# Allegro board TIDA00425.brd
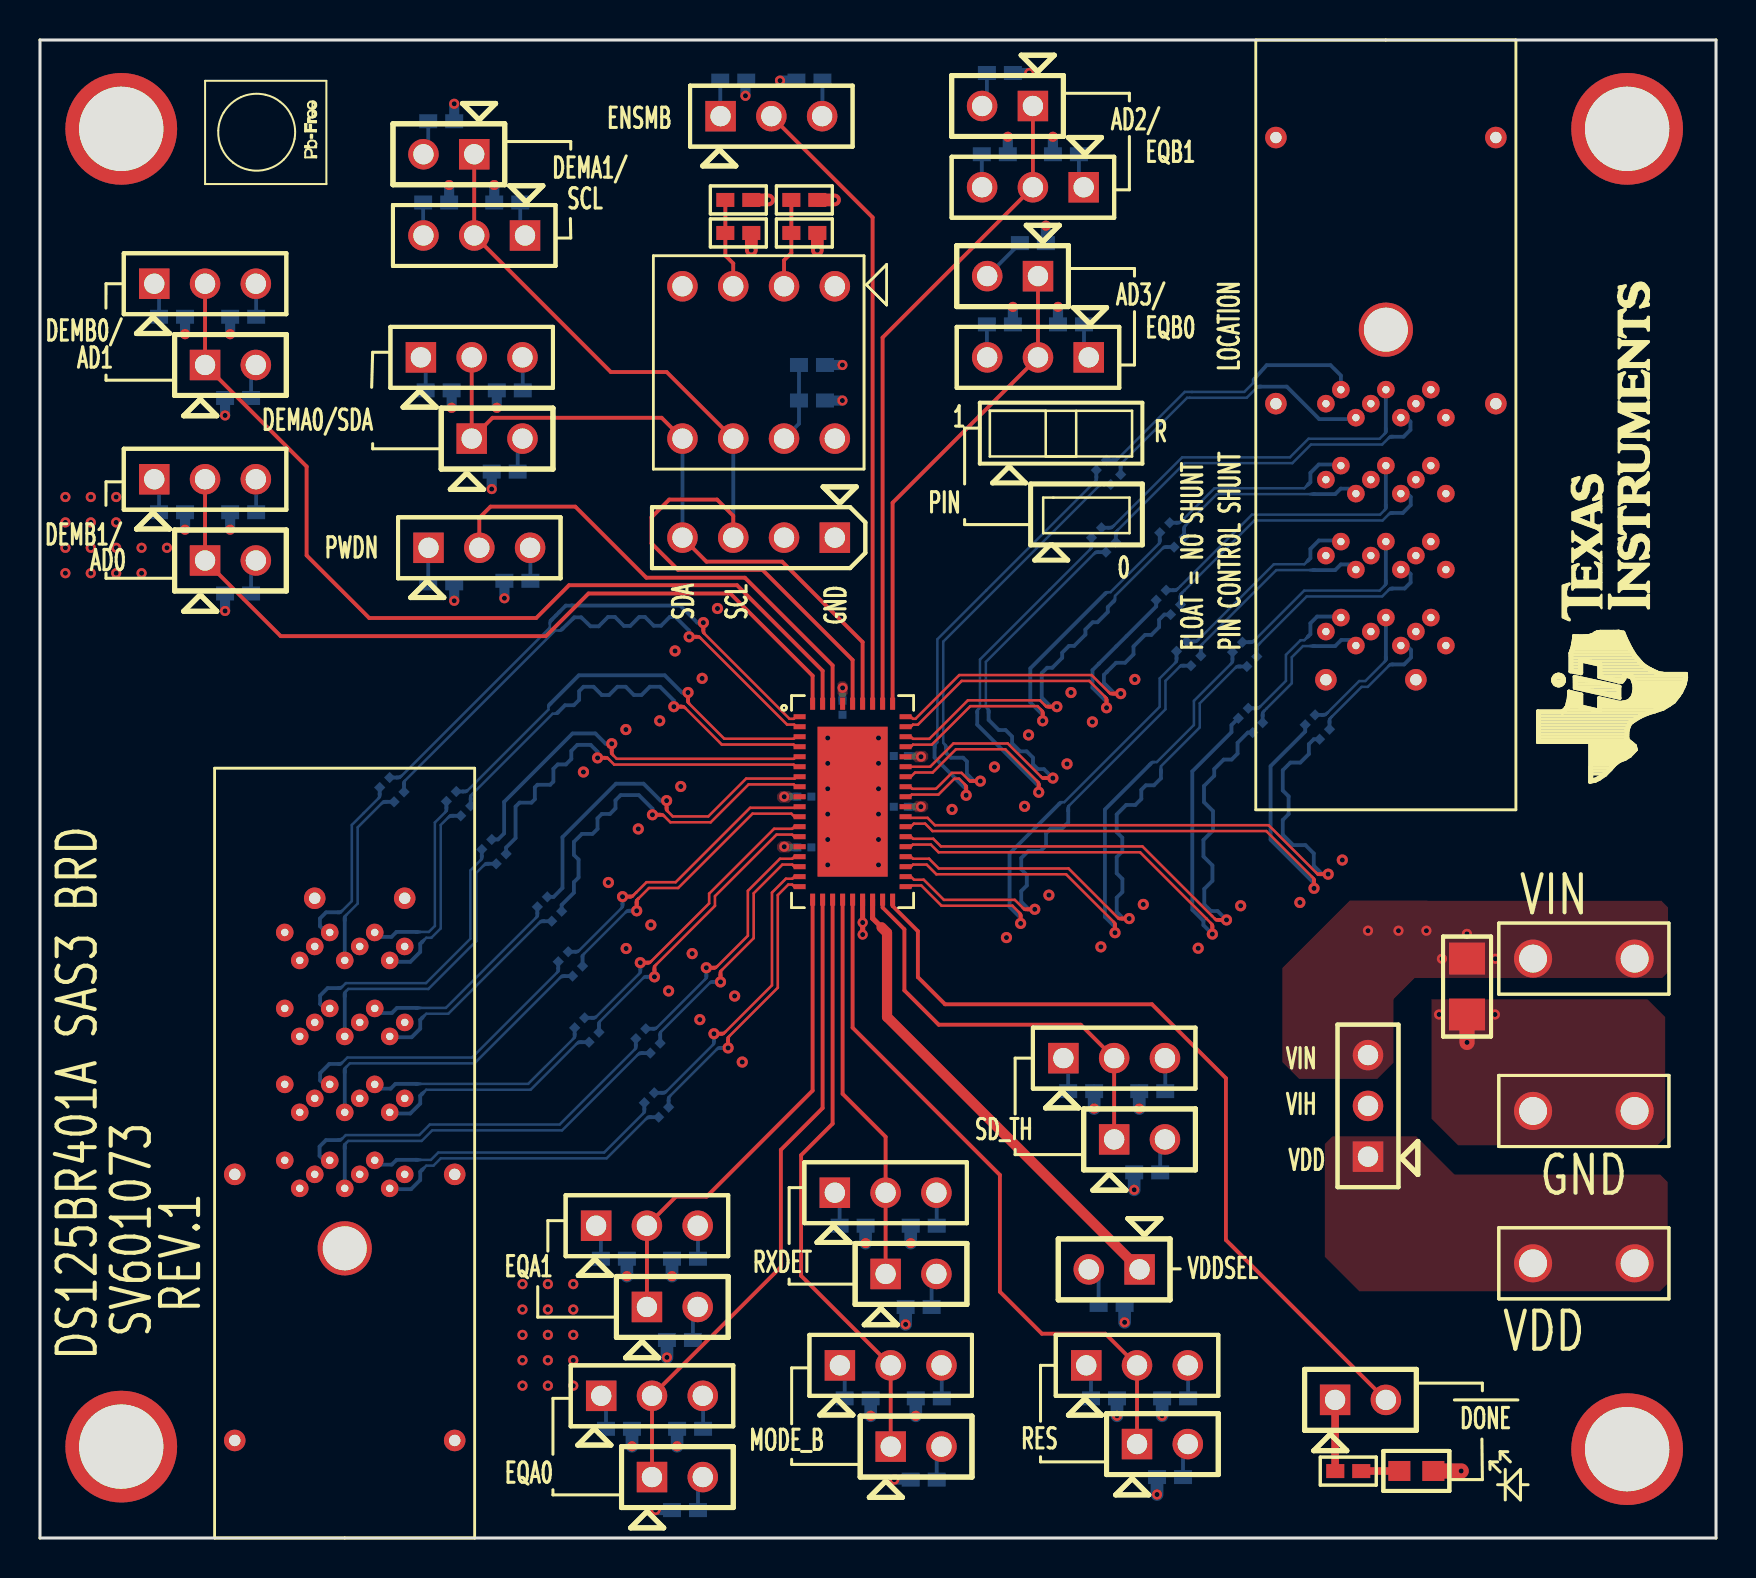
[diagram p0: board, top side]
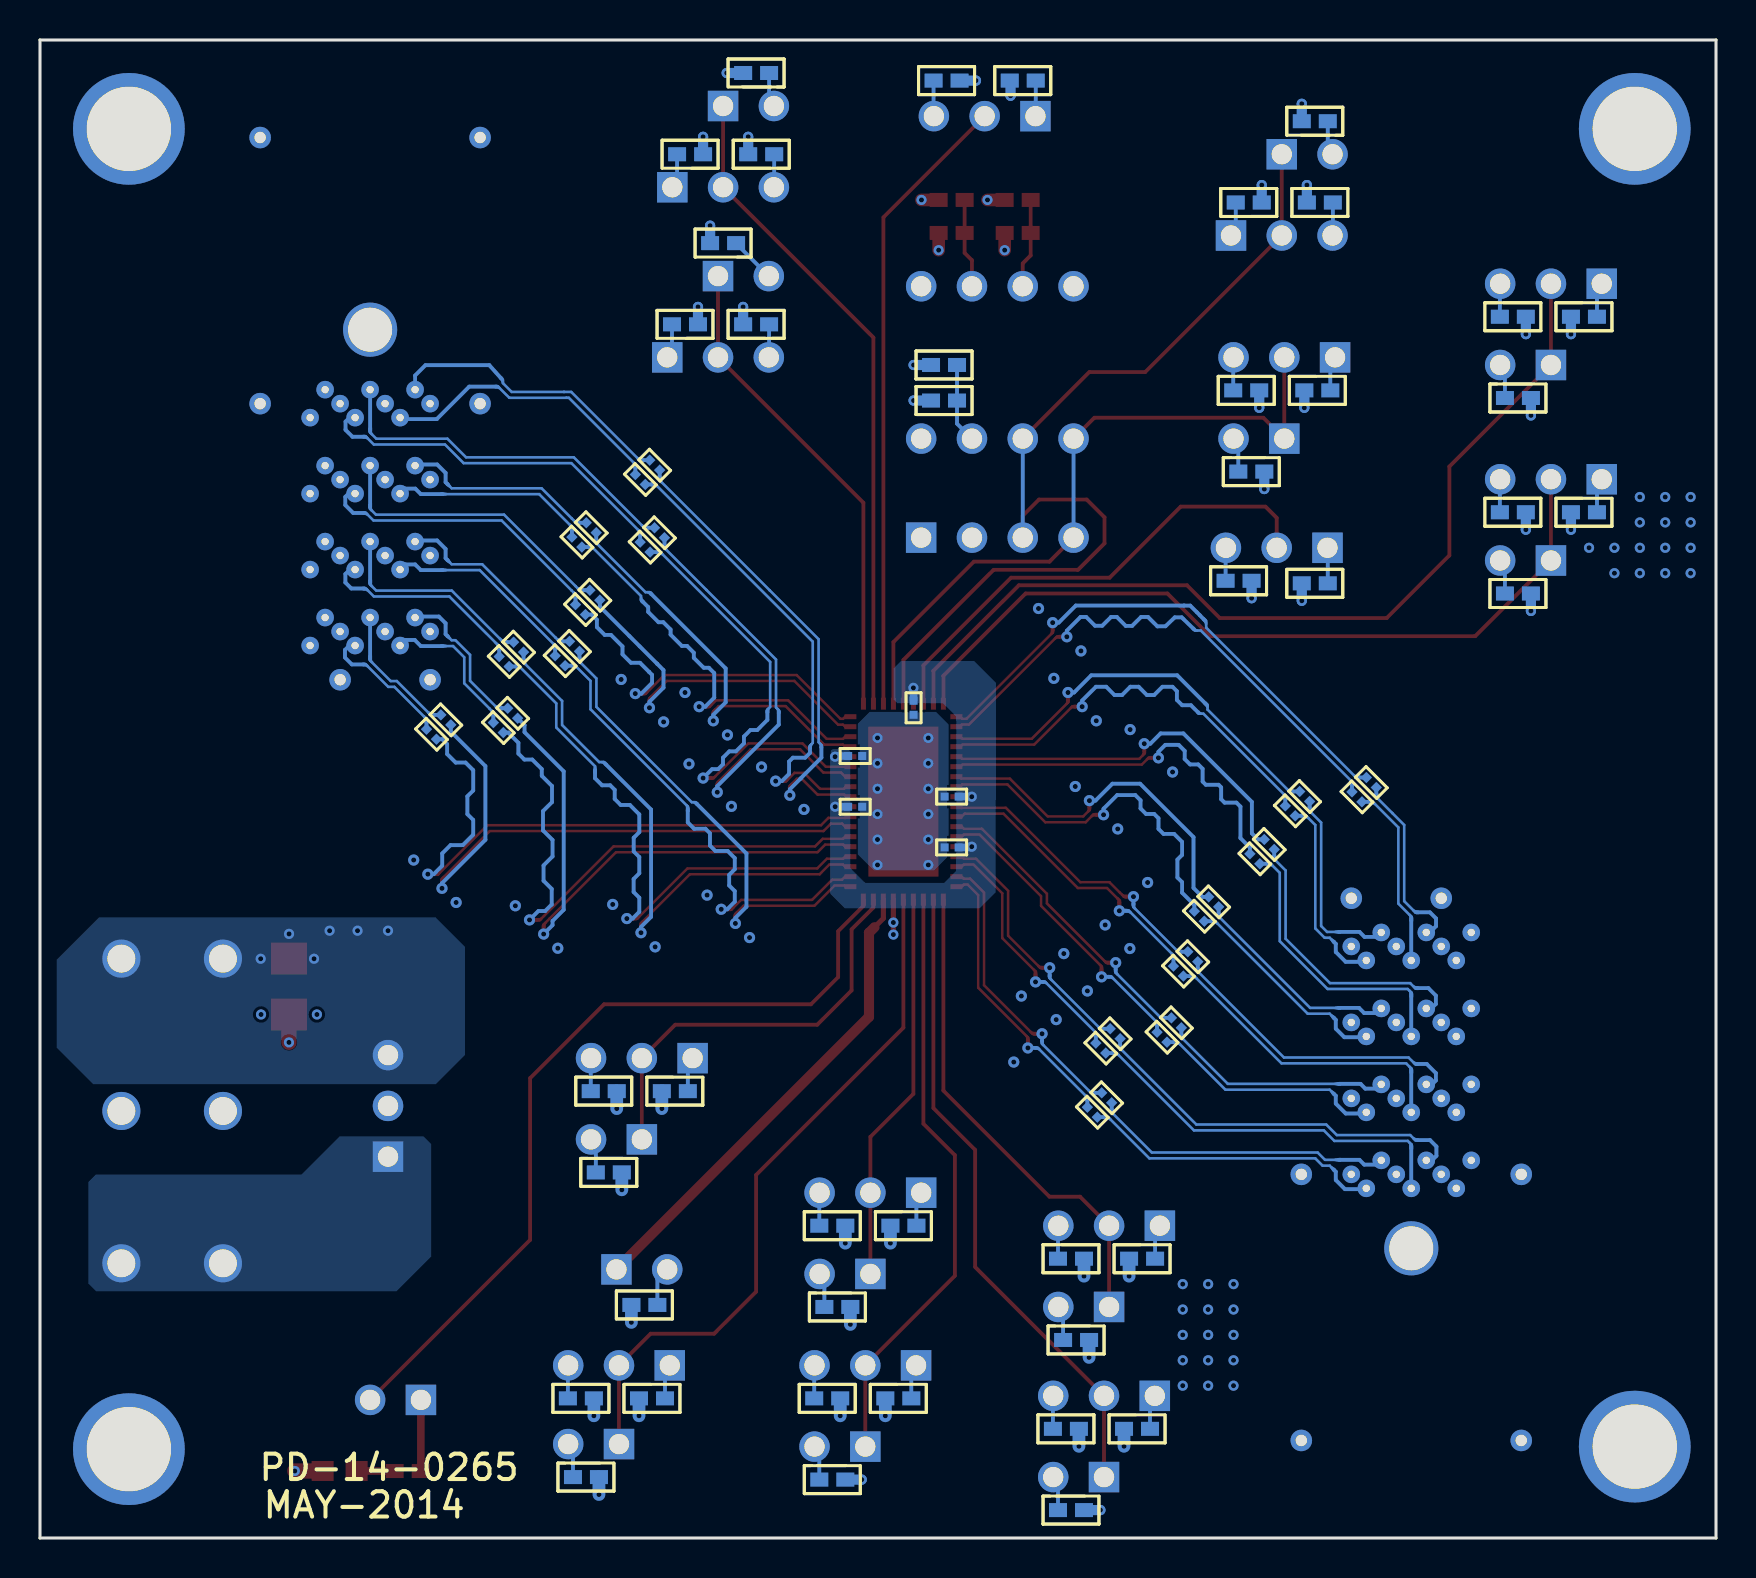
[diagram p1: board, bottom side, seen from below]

Outline 83.82 x 74.93 mm; copper layers: TOP, GND1, PWR, SIGNAL, GND2, BOTTOM. Coordinates in mm from the lower left corner of the outline.
Outline path: 0,74.93 0,0 83.82,0 83.82,74.93 0,74.93

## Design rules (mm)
net group J1: nets IA0N IA0P IA1N IA1P IA2N IA2P IA3N IA3P IA_0N IA_0P IA_1N IA_1P IA_2N IA_2P IA_3N IA_3P OB0N OB0P OB1N OB1P OB2N OB2P OB3N OB3P OB_0N OB_0P OB_1N OB_1P OB_2N OB_2P
net group J2: nets IB0N IB0P IB1N IB1P IB2N IB2P IB3N IB3P IB_0N IB_0P IB_2N IB_2P OA0N OA0P OA1N OA1P OA2N OA2P OA3N OA3P OA_1N OA_1P OA_2N OA_2P OA_3N OA_3P

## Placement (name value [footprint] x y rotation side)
C1  100n  [0201]  17.24 37.79 45 bottom
C2  100n  [0201]  17.96 37.07 45 bottom
C3  100n  [0201]  20.57 37.09 45 bottom
C4  100n  [0201]  21.29 36.37 45 bottom
C5  100n  [0201]  22.34 34.69 45 bottom
C6  100n  [0201]  23.06 33.97 45 bottom
C7  100n  [0201]  25.12 31.82 45 bottom
C8  100n  [0201]  25.84 31.1 45 bottom
C9  100n  [0201]  56.79 46.44 45 bottom
C10  100n  [0201]  56.07 47.16 45 bottom
C11  100n  [0201]  56.97 49.82 45 bottom
C12  100n  [0201]  56.25 50.53 45 bottom
C13  100n  [0201]  53.56 49.56 45 bottom
C14  100n  [0201]  52.84 50.28 45 bottom
C15  100n  [0201]  53.8 52.95 45 bottom
C16  100n  [0201]  53.08 53.66 45 bottom
C17  100n  [0201]  64.24 40.2 45 bottom
C18  100n  [0201]  63.52 40.92 45 bottom
C19  100n  [0201]  60.9 40.54 45 bottom
C20  100n  [0201]  60.18 41.25 45 bottom
C21  100n  [0201]  60.6 43.84 45 bottom
C22  100n  [0201]  59.89 44.56 45 bottom
C23  100n  [0201]  57.81 43.88 45 bottom
C24  100n  [0201]  57.09 44.6 45 bottom
C25  100n  [0201]  26.17 29.08 45 bottom
C26  100n  [0201]  26.88 28.36 45 bottom
C27  100n  [0201]  26.99 25.77 45 bottom
C28  100n  [0201]  27.71 25.05 45 bottom
C29  100n  [0201]  30.05 25.22 45 bottom
C30  100n  [0201]  30.77 24.51 45 bottom
C31  100n  [0201]  30.47 22.02 45 bottom
C32  100n  [0201]  31.19 21.3 45 bottom
C33  100n  [0201]  43.05 36.58 0 bottom
C34  10u  [1206]  71.37 27.58 90 top
C35  100n  [0201]  38.23 34.54 180 bottom
C36  100n  [0201]  38.23 37.08 180 bottom
C37  100n  [0201]  40.13 41.53 90 bottom
C38  100n  [0201]  43.05 39.12 0 bottom
D1  LED  [0603]  68.83 3.35 180 top
J1  miniSAS-HD  [MINISASHD]  15.24 0 90 top
J2  miniSAS-HD  [MINISASHD]  67.31 74.93 270 top
J3  1287-ST  [1287ST]  77.21 21.36 0 top
J4  WM6503-ND  [HEADER3]  66.42 19.07 90 top
J6  WM6503-ND  [HEADER3]  5.72 52.96 0 top
J7  WM6503-ND  [HEADER3]  5.72 62.74 0 top
J8  WM6503-ND  [HEADER3]  24.26 65.15 180 top
J9  WM6503-ND  [HEADER3]  19.05 59.05 0 top
J10  WM6503-ND  [HEADER3]  52.45 59.05 180 top
J11  WM6503-ND  [HEADER3]  27.81 15.62 0 top
J12  WM6502-ND  [HEADER2]  8.26 48.89 0 top
J13  WM6502-ND  [HEADER2]  8.26 58.67 0 top
J14  WM6502-ND  [HEADER2]  21.72 69.22 180 top
J15  WM6502-ND  [HEADER2]  21.59 54.99 0 top
J16  WM6502-ND  [HEADER2]  49.91 63.12 180 top
J17  WM6502-ND  [HEADER2]  30.35 11.56 0 top
J18  WM6503-ND  [HEADER3]  19.43 49.53 0 top
J19  WM6503-ND  [HEADER3]  34.04 71.12 0 top
J21  WM6503-ND  [HEADER3]  39.75 17.27 0 top
J22  WM6502-ND  [HEADER2]  54.99 13.44 180 top
J23  WM6503-ND  [HEADER3]  52.32 8.64 0 top
J24  WM6503-ND  [HEADER3]  51.18 24 0 top
J25  WM6502-ND  [HEADER2]  42.29 13.21 0 top
J26  WM6502-ND  [HEADER2]  54.86 4.7 0 top
J27  WM6502-ND  [HEADER2]  53.72 19.94 0 top
J28  WM6503-ND  [HEADER3]  52.2 67.56 180 top
J29  WM6502-ND  [HEADER2]  49.66 71.63 180 top
J30  WM6502-ND  [HEADER2]  64.77 6.91 0 top
J31  WM6503-ND  [HEADER3]  28.07 7.11 0 top
J32  WM6502-ND  [HEADER2]  30.61 3.05 0 top
J33  WM6503-ND  [HEADER3]  40.01 8.64 0 top
J34  WM6502-ND  [HEADER2]  42.55 4.57 0 top
J35  1287-ST  [1287ST]  77.21 28.98 0 top
J36  1287-ST  [1287ST]  77.21 13.74 0 top
J38  WM6504_ND  [HEADER4]  39.75 50.04 180 top
NOREF  -  []  0 74.93 0 top
NOREF#2  -  [unnamed#2]  79.38 4.45 0 top
NOREF#3  -  [unnamed#2]  4.06 70.48 0 top
NOREF#4  -  [unnamed#2]  79.38 70.48 0 top
NOREF#5  -  [unnamed#2]  4.06 4.57 0 top
NOREF#6  -  []  -176.78 -318.9 0 top
NOREF#7  -  []  83.82 0 90 top
R1  1K  [0402]  6.6 51.31 0 bottom
R2  1K  [0402]  6.6 61.09 0 bottom
R3  1K  [0402]  23.37 66.8 180 bottom
R4  1K  [0402]  19.94 57.4 0 bottom
R5  1K  [0402]  51.56 60.71 180 bottom
R6  1K  [0402]  28.7 13.97 0 bottom
R7  20K  [0402]  10.16 51.31 0 bottom
R8  20K  [0402]  10.16 61.09 0 bottom
R9  20K  [0402]  19.81 66.8 180 bottom
R10  20K  [0402]  23.5 57.4 0 bottom
R11  20K  [0402]  48.01 60.71 180 bottom
R12  20K  [0402]  32.26 13.97 0 bottom
R13  1K  [0402]  9.91 47.24 0 bottom
R14  1K  [0402]  9.91 57.02 0 bottom
R15  1K  [0402]  20.07 70.87 180 bottom
R16  1K  [0402]  23.24 53.34 0 bottom
R17  1K  [0402]  49.66 64.77 180 bottom
R18  1K  [0402]  32 9.91 0 bottom
R19  220  [0402]  65.43 3.35 0 top
R21  1K  [0402]  23.88 47.88 180 bottom
R22  1K  [0402]  20.07 47.75 0 bottom
R23  1K  [0402]  34.67 72.9 180 bottom
R24  1K  [0402]  38.48 72.9 0 bottom
R25  20K  [0402]  44.2 15.62 0 bottom
R26  1K  [0402]  40.64 15.62 0 bottom
R27  1K  [0402]  43.94 11.56 0 bottom
R28  1K  [0402]  53.59 11.66 180 bottom
R29  20K  [0402]  56.77 6.98 0 bottom
R30  1K  [0402]  53.21 6.98 0 bottom
R31  20K  [0402]  55.63 22.35 0 bottom
R32  1K  [0402]  52.07 22.35 0 bottom
R33  1K  [0402]  56.52 3.05 0 bottom
R34  1K  [0402]  55.37 18.29 0 bottom
R35  1K  [0402]  38.23 65.28 0 top
R36  DNP  [0402]  38.23 66.93 180 top
R37  1K  [0402]  34.92 65.28 0 top
R38  DNP  [0402]  34.92 66.93 180 top
R39  DNP  [0402]  38.61 56.9 0 bottom
R40  1K  [0402]  38.61 58.67 180 bottom
R41  20K  [0402]  47.75 69.22 180 bottom
R42  1K  [0402]  51.31 69.22 180 bottom
R43  1K  [0402]  48.01 73.28 180 bottom
R44  20K  [0402]  32.51 5.46 0 bottom
R45  1K  [0402]  28.96 5.46 0 bottom
R46  1K  [0402]  32.26 1.4 0 bottom
R47  20K  [0402]  44.45 6.98 0 bottom
R48  1K  [0402]  40.89 6.98 0 bottom
R49  1K  [0402]  44.2 2.92 0 bottom
U1  DS125BR401A  [QFN54]  40.64 36.83 0 top
U2  24C08  [DIP8-SMT]  35.94 58.8 180 top

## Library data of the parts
C1-C38 = CAP NP
D1 = LED
J1 J2 = HEADER 40_1
J3 J35 J36 = CONN PWR 2-P
J4 J6-J11 J18 J19 J21 J23 J24 J28 J31 J33 = CONN PLUG 3
J12-J17 J22 J25-J27 J29 J30 J32 J34 = CONN PLUG 2
J38 = CON4
R1-R19 R21-R49 = R
U1 = DS3486/SO_2
U2 = 24C08

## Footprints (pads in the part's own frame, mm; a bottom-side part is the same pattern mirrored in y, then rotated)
0201
  rect 0.4x0.4 smd: 1(-0.352,0) 2(0.352,0)
0402
  rect 0.9x0.7 smd: 1(-0.65,0) 2(0.65,0)
0603
  rect 1.1x1 smd: 1(-0.85,0) 2(0.85,0)
1206
  rect 1.6x1.8 smd: 1(-1.4,0) 2(1.4,0)
1287ST
  round 1.905 hole 1.397: 1(-2.54,0) 2(2.54,0)
DIP8-SMT
  round 1.524 hole 1.016: 1(-3.81,-3.81) 2(-1.27,-3.81) 3(1.27,-3.81) 4(3.81,-3.81) 5(3.81,3.81) 6(1.27,3.81) 7(-1.27,3.81) 8(-3.81,3.81)
HEADER2
  rect 1.524x1.524 hole 1.016: 1(0,0)
  round 1.524 hole 1.016: 2(2.54,0)
HEADER3
  rect 1.524x1.524 hole 1.016: 1(0,0)
  round 1.524 hole 1.016: 2(2.54,0) 3(5.08,0)
HEADER4
  rect 1.524x1.524 hole 1.016: 1(0,0)
  round 1.524 hole 1.016: 2(2.54,0) 3(5.08,0) 4(7.62,0)
MINISASHD
  round 1.078 hole 0.57: (4.88,5.5) (4.88,-5.5) (18.19,5.5) (18.19,-5.5) (32,1.5) (32,-3)
  round 2.708 hole 2.2: (14.49,0)
  round 0.878 hole 0.37: A1(18.89,3) A2(17.49,2.25) A3(18.19,1.5) A4(18.89,0.75) A5(17.49,0) A6(18.19,-0.75) A7(18.89,-1.5) A8(17.49,-2.25) A9(18.19,-3) B1(22.69,3) B2(21.29,2.25) B3(21.99,1.5) B4(22.69,0.75) B5(21.29,0) B6(21.99,-0.75) B7(22.69,-1.5) B8(21.29,-2.25) B9(21.99,-3) C1(26.49,3) C2(25.09,2.25) C3(25.79,1.5) C4(26.49,0.75) C5(25.09,0) C6(25.79,-0.75) C7(26.49,-1.5) C8(25.09,-2.25) C9(25.79,-3) D1(30.29,3) D2(28.89,2.25) D3(29.59,1.5) D4(30.29,0.75) D5(28.89,0) D6(29.59,-0.75) D7(30.29,-1.5) D8(28.89,-2.25) D9(29.59,-3)
QFN54
  rect 0.6x0.25 smd: 1(-2.65,4.25) 2(-2.65,3.75) 3(-2.65,3.25) 4(-2.65,2.75) 5(-2.65,2.25) 6(-2.65,1.75) 7(-2.65,1.25) 8(-2.65,0.75) 9(-2.65,0.25) 10(-2.65,-0.25) 11(-2.65,-0.75) 12(-2.65,-1.25) 13(-2.65,-1.75) 14(-2.65,-2.25) 15(-2.65,-2.75) 16(-2.65,-3.25) 17(-2.65,-3.75) 18(-2.65,-4.25) 28(2.65,-4.25) 29(2.65,-3.75) 30(2.65,-3.25) 31(2.65,-2.75) 32(2.65,-2.25) 33(2.65,-1.75) 34(2.65,-1.25) 35(2.65,-0.75) 36(2.65,-0.25) 37(2.65,0.25) 38(2.65,0.75) 39(2.65,1.25) 40(2.65,1.75) 41(2.65,2.25) 42(2.65,2.75) 43(2.65,3.25) 44(2.65,3.75) 45(2.65,4.25)
  rect 0.25x0.6 smd: 19(-2,-4.9) 20(-1.5,-4.9) 21(-1,-4.9) 22(-0.5,-4.9) 23(0,-4.9) 24(0.5,-4.9) 25(1,-4.9) 26(1.5,-4.9) 27(2,-4.9) 46(2,4.9) 47(1.5,4.9) 48(1,4.9) 49(0.5,4.9) 50(0,4.9) 51(-0.5,4.9) 52(-1,4.9) 53(-1.5,4.9) 54(-2,4.9)
  rect 3.51x7.5 smd: 55(0,0)
unnamed#2
  round 5.588 hole 4.216: (0,0)

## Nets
GND: C33.1 C34.1 C35.1 C36.1 C37.1 C38.1 J1.A3(GND#A3) J1.A6(GND#A6) J1.A9(GND#A9) J1.B3(GND#B3) J1.B6(GND#B6) J1.B9(GND#B9) J1.C3(GND#C3) J1.C6(GND#C6) J1.C9(GND#C9) J1.D3(GND#D3) J1.D6(GND#D6) J1.D9(GND#D9) J2.A3(GND#A3) J2.A6(GND#A6) J2.A9(GND#A9) J2.B3(GND#B3) J2.B6(GND#B6) J2.B9(GND#B9) J2.C3(GND#C3) J2.C6(GND#C6) J2.C9(GND#C9) J2.D3(GND#D3) J2.D6(GND#D6) J2.D9(GND#D9) J3.1 J3.2 J38.1 R7.1 R8.1 R9.1 R10.1 R11.1 R12.1 R13.1 R14.1 R15.1 R16.1 R17.1 R18.1 R21.2 R24.1 R25.1 R27.1 R28.1 R29.1 R31.1 R33.1 R34.1 R36.1 R38.1 R40.1 R41.1 R43.1 R44.1 R46.1 R47.1 R49.1 U1.55(GND) U2.1(A0) U2.4(GND)
VDD: C33.2 C35.2 C36.2 C37.2 C38.2 J4.1 J36.1 J36.2 U1.9(VDD#9) U1.14(VDD#14) U1.36(VDD#36) U1.41(VDD#41) U1.51(VDD#51)
VDDSEL: J22.1 U1.25(VDDSEL)
VIN: C34.2 J4.3 J35.1 J35.2 U1.24(VIN)
A1: R35.1 R36.2 U2.2(A1)
A2: R37.1 R38.2 U2.3(A2)
AD0: J6.2 J12.1 U1.54(DEMB1 / AD0)
AD1: J7.2 J13.1 U1.53(DEMB0 / AD1)
AD2: J28.2 J29.1 U1.47(EQB1 / AD2)
AD3: J10.2 J16.1 U1.46(EQB0 / AD3)
DONE: J30.2 U1.27(ALL_DONE)
ENSMB: J19.2 U1.48(ENSMB)
EQA0: J31.2 J32.1 U1.20(EQA0)
EQA1: J11.2 J17.1 U1.19(EQA1)
IA0N: C26.1 J1.B5(RX0_N)
IA0P: C25.1 J1.B4(RX0_P)
IA1N: C30.1 J1.A5(RX1_N)
IA1P: C29.1 J1.A4(RX1_P)
IA2N: C28.1 J1.B8(RX2_N)
IA2P: C27.1 J1.B7(RX2_P)
IA3N: C32.1 J1.A8(RX3_N)
IA3P: C31.1 J1.A7(RX3_P)
IA_0N: C26.2 U1.11(INA_0N)
IA_0P: C25.2 U1.10(INA_0P)
IA_1N: C30.2 U1.16(INA_2N)
IA_1P: C29.2 U1.15(INA_2P)
IA_2N: C28.2 U1.13(INA_1N)
IA_2P: C27.2 U1.12(INA_1P)
IA_3N: C32.2 U1.18(INA_3N)
IA_3P: C31.2 U1.17(INA_3P)
IB0N: C10.2 J2.B5(RX0_N)
IB0P: C9.2 J2.B4(RX0_P)
IB1N: C14.2 J2.A5(RX1_N)
IB1P: C13.2 J2.A4(RX1_P)
IB2N: C12.2 J2.B8(RX2_N)
IB2P: C11.2 J2.B7(RX2_P)
IB3N: C16.2 J2.A8(RX3_N)
IB3P: C15.2 J2.A7(RX3_P)
IB_0N: C10.1 U1.44(INB_0N)
IB_0P: C9.1 U1.45(INB_0P)
IB_1N: C14.1 U1.39(INB_2N)
IB_1P: C13.1 U1.40(INB_2P)
IB_2N: C12.1 U1.42(INB_1N)
IB_2P: C11.1 U1.43(INB_1P)
IB_3N: C16.1 U1.37(INB_3N)
IB_3P: C15.1 U1.38(INB_3P)
INTL: J1.A2(INTL) J2.A2(INTL)
LPBK: J23.2 J26.1 U1.23(LPBK)
MOD: J1.B2(MODPRSL) J2.B2(MODPRSL)
MODE: J33.2 J34.1 U1.21(MODE)
OA0N: C18.2 J2.D5(TX0_N)
OA0P: C17.2 J2.D4(TX0_P)
OA1N: C22.2 J2.C5(TX1_N)
OA1P: C21.2 J2.C4(TX1_P)
OA2N: C20.2 J2.D8(TX2_N)
OA2P: C19.2 J2.D7(TX2_P)
OA3N: C24.2 J2.C8(TX3_N)
OA3P: C23.2 J2.C7(TX3_P)
OA_0N: C18.1 U1.34(OUTA_0N)
OA_0P: C17.1 U1.35(OUTA_0P)
OA_1N: C22.1 U1.30(OUTA_2N)
OA_1P: C21.1 U1.31(OUTA_2P)
OA_2N: C20.1 U1.32(OUTA_1N)
OA_2P: C19.1 U1.33(OUTA_1P)
OA_3N: C24.1 U1.28(OUTA_3N)
OA_3P: C23.1 U1.29(OUTA_3P)
OB0N: C2.1 J1.D5(TX0_N)
OB0P: C1.1 J1.D4(TX0_P)
OB1N: C6.1 J1.C5(TX1_N)
OB1P: C5.1 J1.C4(TX1_P)
OB2N: C4.1 J1.D8(TX2_N)
OB2P: C3.1 J1.D7(TX2_P)
OB3N: C8.1 J1.C8(TX3_N)
OB3P: C7.1 J1.C7(TX3_P)
OB_0N: C2.2 U1.2(OUTB_0N)
OB_0P: C1.2 U1.1(OUTB_0P)
OB_1N: C6.2 U1.6(OUTB_2N)
OB_1P: C5.2 U1.5(OUTB_2P)
OB_2N: C4.2 U1.4(OUTB_1N)
OB_2P: C3.2 U1.3(OUTB_1P)
OB_3N: C8.2 U1.8(OUTB_3N)
OB_3P: C7.2 U1.7(OUTB_3P)
PWDN: J18.2 U1.52(PWDN)
RES1: J1.A1(RES1) J2.A1(RES1)
RXDET: J21.2 J25.1 U1.22(RXDET)
SCL: J8.2 J14.1 J38.3 U1.50(DEMA1 / SCL) U2.6(SCL)
SCLC: J1.C1(SCL) J2.C1(SCL)
SDA: J9.2 J15.1 J38.4 U1.49(DEMA0 / SDA) U2.5(SDA)
SDAC: J1.C2(SDA) J2.C2(SDA)
SDTH: J24.2 J27.1 U1.26(SD_TH / READ_EN)
VACT: J1.B1(VACT#B1) J1.D1(VACT#D1) J2.B1(VACT#B1) J2.D1(VACT#D1)
VIH: D1.1(ANODE) J4.2 R1.2 R2.2 R3.2 R4.2 R5.2 R6.2 R22.2 R23.1 R26.2 R30.2 R32.2 R35.2 R37.2 R39.2 R42.2 R45.2 R48.2 U2.8(VCC)
VMAN: J1.D2(VMAN) J2.D2(VMAN)
WP: R39.1 R40.2 U2.7(WP)
N469503: J6.3 R7.2
N469537: D1.2(CATHODE) R19.2
N469595: J6.1 R1.1
N469811: J7.3 R8.2
N469819: J8.3 R9.2
N469827: J9.3 R10.2
N469835: J10.3 R11.2
N469843: J11.3 R12.2
N469847: J10.1 R5.1
N469855: J11.1 R6.1
N469867: J9.1 R4.1
N469875: J8.1 R3.1
N469883: J7.1 R2.1
N469925: J13.2 R14.2
N469953: J12.2 R13.2
N469977: J14.2 R15.2
N470001: J15.2 R16.2
N470025: J16.2 R17.2
N470049: J17.2 R18.2
N470163: J30.1 R19.1
N470231: J18.1 R22.1
N470235: J18.3 R21.1
N470313: J19.1 R23.2
N470329: J19.3 R24.2
N470353: J21.3 R25.2
N470405: J21.1 R26.1
N470413: J25.2 R27.2
N470453: J22.2 R28.2
N470501: J23.3 R29.2
N470525: J23.1 R30.1
N470567: J24.3 R31.2
N470597: J24.1 R32.1
N470693: J27.2 R34.2
N470705: J26.2 R33.2
N472799: J28.3 R41.2
N472807: J28.1 R42.1
N472815: J29.2 R43.2
N477528: J31.3 R44.2
N477536: J31.1 R45.1
N477544: J32.2 R46.2
N478062: J33.3 R47.2
N478086: J33.1 R48.1
N478094: J34.2 R49.2

Pads without a net: J38 2

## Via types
v1: diameter 0.508, hole 0.254, TOP to BOTTOM, 106 vias
v2: diameter 0.559, hole 0.254, TOP to BOTTOM, 64 vias

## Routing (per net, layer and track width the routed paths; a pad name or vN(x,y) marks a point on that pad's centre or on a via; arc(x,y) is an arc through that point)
GND: length 27.3
  TOP w0.635: R38.1 v1(36.43,66.93) ; R36.1 v1(39.74,66.93)
  TOP w0.762: C34.1 v1(71.37,24.79)
  BOTTOM w0.508: R16.1 v1(22.59,52.47) ; R11.1 v1(48.66,61.58) ; R10.1 v1(22.85,56.53) ; R24.1 v1(37.01,72.9) ; R15.1 v1(20.72,71.74) ; R14.1 v1(9.26,56.15) ; R43.1 v1(49.48,73.28) ; R7.1 v1(9.51,50.44) ; R49.1 v1(42.73,2.92) ; R46.1 v1(30.79,1.4) ; R13.1 v1(9.26,46.37) ; R21.2 v1(23.23,47.01) ; R17.1 v1(50.31,65.64) ; R40.1 v1(40.13,58.67) ; R41.1 v1(48.4,70.09) ; R9.1 v1(20.46,67.67) ; R8.1 v1(9.51,60.22)
  BOTTOM w0.635: R33.1 v1(55.87,2.18) ; R31.1 v1(54.98,21.48) ; R28.1 v1(54.24,10.79) ; R18.1 v1(31.35,9.03) ; R29.1 v1(56.12,6.11) ; R47.1 v1(43.8,6.11) ; R25.1 v1(43.55,14.75) ; R44.1 v1(31.86,4.59) ; R27.1 v1(43.29,10.69) ; R34.1 v1(54.72,17.42) ; R12.1 v1(31.61,13.1)
  vias: v1(39.4,40.02) v1(39.4,38.75) v1(39.4,37.48) v1(39.4,36.21) v1(39.4,34.94) v1(39.4,33.67) v1(41.94,40.02) v1(41.94,38.75) v1(41.94,37.48) v1(41.94,36.21) v1(41.94,34.94) v1(41.94,33.67) v1(69.97,26.19) v1(72.77,26.19) v2(27.18,38.32) v2(28.43,32.79) v2(29.3,40.44) v2(29.32,29.49) v2(29.92,35.47) v2(30.55,30.66) v2(30.99,40.88) v2(31.44,27.36) v2(31.76,44.37) v2(32.04,37.59) v2(32.62,29.23) v2(33,25.93) v2(33.12,43) v2(33.88,46.49) v2(34.74,27.11) v2(35.12,23.81) v2(45.61,36.44) v2(47.73,38.57) v2(48.33,30.03) v2(49.24,36.6) v2(49.44,40.17) v2(50.46,32.16) v2(51.36,38.72) v2(51.56,42.29) v2(52.63,40.82) v2(53.06,29.57) v2(54.76,42.94) v2(55.18,31.69) v2(57.92,29.5) v2(60.05,31.62) v2(63.01,31.79) v2(65.13,33.91)
VDD: length 3.3
  BOTTOM w0.381: v1(40.14,42.52) 40.13,42.52 C37.2 ; v1(37.22,37.08) 37.23,37.08 C36.2 ; C33.2 44.05,36.58 44.06,36.58 v1(44.05,36.58) ; v1(44.06,39.08) 44.02,39.12 C38.2 ; C35.2 37.26,34.54 v1(37.22,34.58)
VDDSEL: length 24
  TOP w0.254: 42.09,30.55 41.64,31 U1.25
  TOP w0.508: J22.1 42.36,26.07 42.36,30.27 42.09,30.55
VIN: length 1.7
  TOP w0.254: U1.24 41.14,30.79 v1(41.14,30.79) v1(41.14,30.18)
  vias: v1(66.42,30.38) v1(67.94,30.38) v1(69.34,30.38) v1(70.11,28.97) v1(71.36,30.22) v1(72.78,28.97)
A1: length 4.5
  TOP w0.191: U2.2 37.21,63.91 37.58,64.28 R35.1 R36.2
A2: length 4.5
  TOP w0.191: R38.2 R37.1 34.28,64.15 34.67,63.76 U2.3
AD0: length 40
  TOP w0.191: U1.54 38.64,43.13 34.52,47.24 27.43,47.24 25.3,45.11 12.04,45.11 J12.1 J6.2
AD1: length 46.9
  TOP w0.191: J7.2 J13.1 13.34,53.59 13.34,49.15 16.47,46.02 24.82,46.02 26.46,47.66 34.86,47.66 39.14,43.38 U1.53
AD2: length 33
  TOP w0.191: U1.47 42.14,60.05 J28.2 J29.1
AD3: length 24.4
  TOP w0.191: U1.46 42.64,51.78 J10.2 J16.1
DONE: length 41.3
  TOP w0.191: U1.27 42.64,31.62 43.9,30.35 43.9,28.05 45.26,26.7 55.61,26.7 59.31,23 59.31,14.91 J30.2
ENSMB: length 31.5
  TOP w0.191: J19.2 41.64,66.06 U1.48
EQA0: length 32.4
  TOP w0.191: U1.20 39.14,21.5 37.05,19.42 37.05,13.56 30.61,7.11 J32.1
EQA1: length 24.7
  TOP w0.191: J17.1 30.35,15.62 31.81,17.07 33.34,17.07 38.64,22.38 U1.19
IA0N: length 15.5
  BOTTOM w0.127: 26.22,28.11 26.09,28.11 21.73,23.74 15.5,23.74 15.24,23.49 15.24,23.41
  BOTTOM w0.191: 26.22,28.11 C26.1 ; J1.B5 15.24,21.29 15.24,23.41
IA0P: length 15.4
  BOTTOM w0.127: 15,23.71 15.05,23.71 15.37,24.03 21.61,24.03 25.92,28.35 25.92,28.5
  BOTTOM w0.191: J1.B4 14.2,22.69 14.01,22.89 14.01,23.25 14.47,23.71 15,23.71 ; 25.92,28.5 C25.1
IA1N: length 19.4
  BOTTOM w0.127: 15.24,19.61 15.24,19.69 15.41,19.86 19.09,19.86 19.61,20.39 26.11,20.39 29.98,24.26 30.11,24.26
  BOTTOM w0.191: J1.A5 15.24,17.49 15.24,19.61 ; C30.1 30.11,24.26
IA1P: length 19.4
  BOTTOM w0.127: 29.8,24.64 29.8,24.49 25.99,20.68 19.49,20.68 18.97,20.15 15.29,20.15 15.04,19.9 14.9,19.9
  BOTTOM w0.191: 14.9,19.9 14.3,19.9 13.98,19.58 13.98,19.11 14.21,18.89 J1.A4 ; C29.1 29.8,24.64
IA2N: length 11.7
  BOTTOM w0.127: 27.04,24.8 26.91,24.8 24.54,22.42 19.32,22.42 19.12,22.23
  BOTTOM w0.191: C28.1 27.46,24.8 27.04,24.8 ; 19.12,22.23 19.01,22.12 19.01,21.73 18.52,21.23 17.55,21.23 J1.B8
IA2P: length 11.6
  BOTTOM w0.127: 26.74,25.19 26.74,25.04 24.42,22.72 18.86,22.72
  BOTTOM w0.191: 18.86,22.72 17.78,22.72 17.54,22.48 16.95,22.48 J1.B7 ; 26.74,25.19 C27.1
IA3N: length 15.2
  BOTTOM w0.127: 30.53,21.05 30.4,21.05 28.34,18.99 20.04,18.99 19.68,18.62 19.32,18.62 19.12,18.43
  BOTTOM w0.191: J1.A8 17.53,17.45 18.56,17.45 19.01,17.91 19.01,18.32 19.12,18.43 ; C32.1 30.53,21.05
IA3P: length 15.1
  BOTTOM w0.127: 30.22,21.44 30.22,21.29 28.22,19.28 19.92,19.28 19.55,18.92 18.86,18.92
  BOTTOM w0.191: 30.22,21.44 C31.1 ; 18.86,18.92 17.83,18.92 17.59,18.68 16.95,18.68 J1.A7
IA_0N: length 14.8
  TOP w0.127: U1.11 37.73,36.08 37.58,36.23 35.63,36.23 31.91,32.51 30.46,32.51 29.95,32 29.82,31.87 29.93,31.99
  TOP w0.191: v2(29.84,31.37) 29.84,31.8
  BOTTOM w0.127: 29.48,31.37 29.36,31.37 27.13,29.15 27.13,29.1
  BOTTOM w0.191: C26.2 27.13,29.1 ; 29.48,31.37 v2(29.84,31.37)
IA_0P: length 14.9
  TOP w0.127: 29.63,32.11 29.61,32.08 29.53,32.08 ; 29.64,32.11 29.65,32.12 29.81,32.28 29.81,32.28 30.33,32.8 31.79,32.8 35.51,36.52 37.73,36.52 37.78,36.58 U1.10
  TOP w0.191: v2(29.13,32.08) 29.53,32.08
  BOTTOM w0.127: 29.13,31.69 29.13,31.56 26.9,29.32 26.78,29.32
  BOTTOM w0.191: v2(29.13,32.08) 29.13,31.69 ; 26.78,29.32 C25.2
IA_1N: length 12.7
  TOP w0.127: 34.03,28.19 34.03,28.34 35.69,30 35.69,32.25 37.13,33.68 37.62,33.68 37.73,33.58 U1.16
  TOP w0.191: 34.03,28.19 v2(34.03,27.82)
  BOTTOM w0.127: 31.02,25.19 31.02,25.28 33.55,27.82 33.65,27.82
  BOTTOM w0.191: C30.2 31.02,25.19 ; 33.65,27.82 v2(34.03,27.82)
IA_1P: length 12.9
  TOP w0.127: 33.72,28.52 33.8,28.52 35.4,30.13 35.4,32.37 37.01,33.98 37.62,33.98 37.72,34.08 U1.15
  TOP w0.191: v2(33.32,28.52) 33.72,28.52
  BOTTOM w0.127: 33.32,28.1 33.32,28.01 30.79,25.47 30.71,25.47
  BOTTOM w0.191: 30.71,25.47 30.3,25.47 C29.2 ; v2(33.32,28.52) 33.32,28.1
IA_2N: length 15.1
  TOP w0.127: 30.73,28.44 30.73,28.6 33.76,31.62 33.76,32.11 36.83,35.18 37.62,35.18 37.72,35.08 U1.13
  TOP w0.191: v2(30.73,28.07) 30.73,28.44
  BOTTOM w0.127: 30.35,28.07 30.23,28.07 27.96,25.8 27.96,25.63
  BOTTOM w0.191: 30.35,28.07 v2(30.73,28.07) ; C28.2 27.96,25.63
IA_2P: length 15.3
  TOP w0.127: U1.12 37.73,35.58 37.62,35.48 36.71,35.48 33.46,32.23 33.46,31.74 30.5,28.78 30.42,28.78
  TOP w0.191: 30.42,28.78 v2(30.02,28.78)
  BOTTOM w0.127: 27.65,26.02 27.76,26.02 30.02,28.28 30.02,28.44
  BOTTOM w0.191: C27.2 27.24,26.02 27.65,26.02 ; 30.02,28.44 v2(30.02,28.78)
IA_3N: length 14.5
  TOP w0.127: 34.41,24.89 34.41,25.04 36.9,27.53 36.9,32.16 37.42,32.68 37.62,32.68 37.72,32.58 U1.18
  TOP w0.191: 34.41,24.89 v2(34.41,24.51)
  BOTTOM w0.127: 31.44,21.88 31.44,22.04 33.91,24.51 34.03,24.51 34.04,24.51
  BOTTOM w0.191: 31.44,21.88 C32.2 ; v2(34.41,24.51) 34.04,24.51
IA_3P: length 14.8
  TOP w0.127: 34.1,25.22 34.18,25.22 36.61,27.65 36.61,32.28 37.3,32.98 37.62,32.98 37.73,33.08 U1.17
  TOP w0.191: v2(33.71,25.22) 34.1,25.22
  BOTTOM w0.127: 31.13,22.27 31.25,22.27 33.71,24.72 33.71,24.88
  BOTTOM w0.191: v2(33.71,25.22) 33.71,24.88 ; 31.13,22.27 C31.2
IB0N: length 14.8
  BOTTOM w0.127: 56.7,47.41 56.83,47.41 56.9,47.48 60.61,51.19 67.02,51.19 67.31,51.48 67.31,51.57
  BOTTOM w0.191: C10.2 56.54,47.41 56.7,47.41 ; 67.31,51.57 67.31,53.64 J2.B5
IB0P: length 14.8
  BOTTOM w0.127: 67.61,51.27 67.52,51.27 67.14,50.9 60.73,50.9 57.25,47.41 57.11,47.27 57.04,47.2 57.04,47.09
  BOTTOM w0.191: 67.61,51.27 68.16,51.27 68.55,51.67 68.55,52.08 68.39,52.24 J2.B4 ; 57.04,47.09 C9.2
IB1N: length 18.3
  BOTTOM w0.127: 67.31,55.37 67.31,55.29 67,54.99 63.44,54.99 62.51,54.06 57.12,54.06 53.71,50.64 53.67,50.6 53.6,50.53 53.46,50.53
  BOTTOM w0.191: J2.A5 67.31,57.44 67.31,55.37 ; 53.46,50.53 C14.2
IB1P: length 18.3
  BOTTOM w0.127: 67.57,55.08 67.51,55.08 67.12,54.69 63.56,54.69 62.63,53.76 57.24,53.76 53.88,50.4 53.81,50.33 53.81,50.22
  BOTTOM w0.191: J2.A4 68.34,56.04 68.54,55.84 68.54,55.43 68.19,55.08 67.57,55.08 ; 53.81,50.22 C13.2
IB2N: length 10.1
  BOTTOM w0.127: 56.87,50.78 57.01,50.78 57.08,50.85 57.22,50.99 58.73,52.51 63.23,52.51 63.43,52.7
  BOTTOM w0.191: J2.B8 65,53.7 63.95,53.7 63.54,53.28 63.54,52.81 63.43,52.7 ; C12.2 56.87,50.78
IB2P: length 10
  BOTTOM w0.127: 63.69,52.21 58.86,52.21 57.29,50.65 57.22,50.58 57.22,50.47
  BOTTOM w0.191: C11.2 57.22,50.47 ; 63.69,52.21 64.77,52.21 65.05,52.49 65.56,52.49 J2.B7
IB3N: length 14.7
  BOTTOM w0.127: 60.76,58.01 60.69,57.91 60.67,57.77 60.23,57.33 57.61,57.33 57.25,57.33 53.91,53.98 53.84,53.91 53.7,53.91
  BOTTOM w0.191: 53.7,53.91 C16.2 ; 60.76,58.01 61.35,58.66 64.54,58.66 65.06,58.15 J2.A8
IB3P: length 14.6
  BOTTOM w0.127: 54.04,53.6 54.04,53.71 57.37,57.03 57.49,57.03 60.35,57.03 60.91,57.59 60.98,57.59
  BOTTOM w0.191: J2.A7 65.74,55.97 63.98,55.97 62.35,57.59 60.98,57.59 ; C15.2 54.04,53.6
IB_0N: length 18.8
  TOP w0.127: U1.44 43.55,40.58 43.66,40.68 43.91,40.68 46.09,42.87 52.47,42.87 53.3,42.05 53.34,42 53.34,41.93
  TOP w0.191: v2(53.34,41.53) 53.34,41.93
  BOTTOM w0.191: C10.1 55.82,46.59 54.34,45.12 53.83,44.6 52.64,43.41 52.64,42.54 53.34,41.83 v2(53.34,41.53)
IB_0P: length 18.6
  TOP w0.127: 53.67,42.24 53.52,42.24 52.6,43.16 45.97,43.16 43.79,40.98 43.66,40.98 43.55,41.08 U1.45
  TOP w0.191: v2(54.05,42.24) 53.67,42.24
  BOTTOM w0.191: v2(54.05,42.24) 53.74,42.24 53.21,42.77 53.21,43.17 53.36,43.33 53.81,43.78 54.27,43.78 54.69,44.2 54.69,44.6 55.26,45.17 55.58,45.17 55.97,45.56 55.97,45.93 56.23,46.19 C9.1
IB_1N: length 24.8
  TOP w0.127: U1.39 43.55,38.08 43.76,38.29 44.64,38.29 45.81,39.45 48.28,39.45 49.95,37.78 49.95,37.7
  TOP w0.191: 49.95,37.7 v2(49.95,37.3)
  BOTTOM w0.127: 46.87,41.33 46.87,41.4 47.01,41.54 47.01,43.94 50.49,47.42 52.59,49.52 52.59,49.63
  BOTTOM w0.191: C14.1 52.59,49.63 ; v2(49.95,37.3) 49.95,37.61 46.87,40.68 46.87,41.33
IB_1P: length 24.6
  TOP w0.127: 50.28,38.01 50.13,38.01 48.4,39.74 45.69,39.74 44.52,38.58 U1.40
  TOP w0.191: 50.28,38.01 v2(50.66,38.01)
  BOTTOM w0.127: 52.93,49.32 52.8,49.32 47.3,43.82 47.3,41.57 47.44,41.43 47.44,41.37
  BOTTOM w0.191: C13.1 52.93,49.32 ; 47.44,41.37 47.44,40.92 47.95,40.41 48.29,40.41 48.61,40.09 48.61,39.75 49.01,39.35 49.34,39.35 49.66,39.03 49.66,38.7 49.91,38.46 50.21,38.46 v2(50.66,38.01)
IB_2N: length 20.7
  TOP w0.127: 50.15,41.27 50.15,41.35 50.12,41.38 49.89,41.61 46.53,41.61 44.6,39.68 43.66,39.68 43.56,39.58 U1.42
  TOP w0.191: v2(50.15,40.88) 50.15,41.27
  BOTTOM w0.127: 53.28,47.25 53.34,47.31 53.54,47.31 56,49.77 56,49.88
  BOTTOM w0.191: 53.28,47.25 49.53,43.5 49.53,41.8 50.15,41.18 v2(50.15,40.88) ; 56,49.88 C12.1
IB_2P: length 20.5
  TOP w0.127: U1.43 43.55,40.08 43.66,39.98 44.48,39.98 46.41,41.9 50.01,41.9 50.33,41.58 50.48,41.58
  TOP w0.191: v2(50.85,41.58) 50.48,41.58
  BOTTOM w0.127: 56.34,49.57 56.21,49.57 53.76,47.12 53.76,46.92 53.72,46.88
  BOTTOM w0.191: 56.34,49.57 C11.1 ; 53.72,46.88 53.4,46.56 53.4,46.32 52.89,45.81 52.65,45.81 52.28,45.44 52.28,45.19 51.72,44.62 51.46,44.62 51.12,44.28 51.12,44.03 50.62,43.53 50.37,43.53 50.1,43.26 50.1,42.03 50.55,41.58 v2(50.85,41.58)
IB_3N: length 24.3
  TOP w0.127: U1.37 43.49,37.08 43.59,37.18 44.93,37.18 45.73,37.98 45.97,37.98 46.32,37.63 46.32,37.55
  TOP w0.191: 46.32,37.55 v2(46.32,37.15)
  BOTTOM w0.127: 44.74,39.57 44.74,39.66 44.88,39.8 44.88,44.96 47.32,47.4 52.83,52.9 52.83,53.06
  BOTTOM w0.191: 44.74,39.57 44.74,39.03 45.79,37.99 45.79,37.98 46.32,37.45 v2(46.32,37.15) ; C16.1 52.83,53.06
IB_3P: length 24.2
  TOP w0.127: 46.63,37.86 46.5,37.86 46.09,38.27 45.61,38.27 44.81,37.48 43.62,37.48 43.52,37.58 U1.38
  TOP w0.191: 46.63,37.86 v2(47.03,37.86)
  BOTTOM w0.127: 53.18,52.7 53.03,52.7 45.17,44.83 45.17,39.77 45.29,39.66 45.29,39.59 45.31,39.56
  BOTTOM w0.191: C15.1 53.18,52.7 ; v2(47.03,37.86) 46.72,37.86 46.36,38.22 46.36,38.84 46.17,39.03 45.55,39.03 45.31,39.27 45.31,39.56
INTL: length 98.9
  SIGNAL w0.178: J2.A2 68.73,58.27 54.79,58.27 49.23,52.7 24.51,52.7 23.52,53.7 18.79,53.7 6.17,41.08 6.17,22.98 11.66,17.49 J1.A2
LPBK: length 35
  TOP w0.191: U1.23 40.64,25.53 48.01,18.16 48.01,12.32 50.11,10.22 53.28,10.22 J23.2 J26.1
MOD: length 90.6
  SIGNAL w0.178: J1.B2 11.52,21.29 7.68,25.13 7.68,40.74 18.5,51.56 49.87,51.56 52.98,54.68 68.52,54.68 J2.B2
MODE: length 29.9
  TOP w0.191: J34.1 J33.2 38.06,13.12 38.06,19.15 39.64,20.72 U1.21
OA0N: length 6.8
  BOTTOM w0.127: 64.15,41.17 64.28,41.17 64.35,41.24 65.98,42.87 66.28,42.87 67.31,43.89 67.31,43.97
  BOTTOM w0.191: 67.31,43.97 67.31,43.97 J2.D5 ; C18.2 64.15,41.17
OA0P: length 6.8
  BOTTOM w0.127: 67.63,43.7 67.62,43.69 67.51,43.69 66.4,42.57 66.1,42.57 64.61,41.09 64.49,40.97 64.49,40.86
  BOTTOM w0.191: J2.D4 68.35,44.64 68.57,44.42 68.57,44.04 68.22,43.7 67.63,43.7 ; 64.49,40.86 C17.2
OA1N: length 10.5
  BOTTOM w0.127: 67.31,47.77 67.31,47.69 67,47.39 63.23,47.39 60.81,44.97 60.65,44.81 60.51,44.81 ; 60.13,44.81 C22.2
  BOTTOM w0.191: 67.31,47.77 67.31,49.84 J2.C5 ; 60.51,44.81 60.13,44.81
OA1P: length 10.5
  BOTTOM w0.127: 60.85,44.49 60.85,44.6 60.92,44.67 61.02,44.76 61.02,44.77 63.35,47.1 67.12,47.1 67.5,47.47 67.6,47.47 67.61,47.49
  BOTTOM w0.191: 60.85,44.49 C21.2 ; 67.61,47.49 68.25,47.49 68.55,47.79 68.55,48.22 68.33,48.44 J2.C4
OA2N: length 7.6
  BOTTOM w0.127: 60.8,41.5 60.94,41.5 61.01,41.57 62.31,42.88 62.31,44.18 63.04,44.91 63.23,44.91 63.43,45.1
  BOTTOM w0.191: 63.43,45.1 63.54,45.21 63.54,45.75 63.87,46.09 65.01,46.09 J2.D8 ; C20.2 60.69,41.5 60.8,41.5
OA2P: length 7.6
  BOTTOM w0.127: 63.69,44.61 63.16,44.61 62.6,44.06 62.6,42.75 61.35,41.5 61.35,41.5 61.22,41.37 61.15,41.3 61.15,41.19
  BOTTOM w0.191: 63.69,44.61 64.77,44.61 65.08,44.92 65.53,44.92 J2.D7 ; 61.15,41.19 C19.2
OA3N: length 10.1
  BOTTOM w0.127: 63.43,48.9 63.23,48.71 61.71,48.71 58.06,45.06 58.06,45.06 57.92,44.92 57.92,44.92 57.85,44.85 57.71,44.85
  BOTTOM w0.191: 63.43,48.9 63.54,49.01 63.54,49.47 63.96,49.9 65,49.9 J2.C8 ; C24.2 57.71,44.85
OA3P: length 10.1
  BOTTOM w0.127: 63.69,48.41 61.83,48.41 58.13,44.71 58.06,44.64 58.06,44.53
  BOTTOM w0.191: J2.C7 65.55,48.7 65.06,48.7 64.77,48.41 63.69,48.41 ; C23.2 58.06,44.53
OA_0N: length 31.9
  TOP w0.127: 63.72,32.89 63.72,32.97 61.33,35.36 44.64,35.36 44.27,35.73 43.7,35.73 43.55,35.58 U1.34
  TOP w0.191: 63.72,32.89 v2(63.72,32.5)
  BOTTOM w0.191: v2(63.72,32.5) 63.72,32.75 61.54,34.92 61.54,38.61 63.27,40.34 C18.1
OA_0P: length 32
  TOP w0.127: 64.05,33.2 63.9,33.2 61.45,35.65 44.76,35.65 44.39,36.02 43.55,36.02 43.49,36.08 U1.35
  TOP w0.191: 64.05,33.2 v2(64.42,33.2)
  BOTTOM w0.191: v2(64.42,33.2) 64.13,33.2 63.7,33.63 63.7,34.24 63.29,34.66 62.68,34.66 62.15,35.18 62.15,35.92 62.45,36.21 62.45,37.1 62.15,37.39 62.15,38.4 62.53,38.79 63.03,38.79 63.46,39.21 63.46,39.71 63.7,39.96 C17.1
OA_1N: length 29.2
  TOP w0.127: U1.30 43.56,33.58 43.66,33.68 44.34,33.68 44.83,33.2 51.32,33.2 53.76,30.75 53.76,30.67
  TOP w0.191: 53.76,30.67 v2(53.76,30.28)
  BOTTOM w0.127: 59.64,43.98 59.64,43.8 57.71,41.87 57.71,40.67 55.85,38.81 55.63,38.81 55.52,38.7
  BOTTOM w0.191: v2(53.76,30.28) 53.76,30.56 53.26,31.07 53.26,36.44 55.52,38.7 ; C22.1 59.64,43.98
OA_1P: length 29.5
  TOP w0.127: U1.31 43.55,34.08 43.66,33.98 44.46,33.98 44.95,33.49 51.44,33.49 53.94,30.98 54.1,30.98
  TOP w0.191: 54.1,30.98 v2(54.47,30.98)
  BOTTOM w0.127: 59.96,43.59 59.84,43.59 58,41.75 58,40.54 56.06,38.6 56.06,38.41
  BOTTOM w0.191: 56.06,38.41 56.06,38 55.71,37.65 55.3,37.65 55.08,37.43 55.08,36.97 54.78,36.67 54.32,36.67 53.85,36.2 53.85,35.31 54.13,35.03 54.13,34.34 53.85,34.06 53.85,33.25 54.13,32.97 54.13,32.31 53.85,32.03 53.85,31.32 54.18,30.98 v2(54.47,30.98) ; C21.1 59.96,43.59
OA_2N: length 29.7
  TOP w0.127: U1.32 43.55,34.58 43.65,34.68 44.55,34.68 44.94,34.3 55.01,34.3 58.32,30.99 58.63,30.68 58.63,30.6
  TOP w0.191: 58.63,30.6 v2(58.63,30.21)
  BOTTOM w0.191: v2(58.63,30.21) 58.19,30.65 58.19,30.87 57.63,31.42 57.63,38.35 59.59,40.31 59.59,40.66 C20.1
OA_2P: length 29.9
  TOP w0.127: 58.97,30.92 58.81,30.92 58.62,31.11 58.62,31.11 55.14,34.59 45.06,34.59 44.67,34.98 43.66,34.98 43.55,35.08 U1.33
  TOP w0.191: 58.97,30.92 v2(59.34,30.92)
  BOTTOM w0.191: v2(59.34,30.92) 58.89,31.36 58.55,31.36 58.23,31.69 58.23,32.47 58.64,32.87 58.64,33.64 58.19,34.09 58.19,34.92 58.66,35.39 58.66,36.36 58.21,36.81 58.21,37.61 58.72,38.13 58.72,38.46 59.2,38.94 59.6,38.94 59.89,39.24 59.89,39.78 60.4,40.29 C19.1
OA_3N: length 24.2
  TOP w0.127: U1.28 43.54,32.58 43.6,32.64 44.08,32.64 45.09,31.63 48.63,31.63 49.04,31.22 49.04,31.14
  TOP w0.191: 49.04,31.14 v2(49.04,30.74)
  BOTTOM w0.127: 50.98,36.73 51.05,36.8 51.22,36.8 55.99,41.57 55.99,42.99 56.84,43.84 56.84,43.98
  BOTTOM w0.191: v2(49.04,30.74) 49.04,31.02 48.49,31.57 48.49,34.24 50.98,36.73 ; C24.1 56.84,43.98
OA_3P: length 24.5
  TOP w0.127: U1.29 43.56,33.08 43.71,32.93 44.2,32.93 45.21,31.92 48.75,31.92 49.22,31.45 49.38,31.45
  TOP w0.191: 49.38,31.45 v2(49.75,31.45)
  BOTTOM w0.127: 51.42,36.45 51.42,36.59 56.29,41.45 56.29,42.87 57.05,43.63 57.16,43.63
  BOTTOM w0.191: v2(49.75,31.45) 49.45,31.45 49.07,31.83 49.07,32.36 49.35,32.64 49.35,33.17 49.07,33.45 49.07,34.01 49.43,34.37 50.04,34.37 50.31,34.64 50.31,35.25 50.54,35.48 51.11,35.48 51.42,35.79 51.42,36.45 ; C23.1 57.16,43.63
OB0N: length 9.3
  BOTTOM w0.127: 17.29,36.82 17.16,36.82 15.89,35.54 15.89,31.73 15.24,31.09 15.24,31.01
  BOTTOM w0.191: 17.29,36.82 C2.1 ; J1.D5 15.24,28.89 15.24,31.01
OB0P: length 9.2
  BOTTOM w0.127: 16.99,37.21 16.99,37.06 16.19,36.26 15.6,35.67 15.6,31.85 15.04,31.3 ; 15.04,31.3 15.04,31.3 ; 15.04,31.3 14.98,31.3
  BOTTOM w0.191: 14.98,31.3 14.31,31.3 14,30.99 14,30.6 14.32,30.29 J1.D4 ; 16.99,37.21 C1.1
OB1N: length 14.4
  BOTTOM w0.127: 15.24,27.21 15.24,27.29 15.42,27.46 19.43,27.46 21.82,29.85 21.82,33.27 22.27,33.72 22.4,33.72
  BOTTOM w0.191: J1.C5 15.24,25.09 15.24,27.21 ; 22.4,33.72 C6.1
OB1P: length 14.4
  BOTTOM w0.127: 22.09,34.11 22.09,33.96 21.52,33.39 21.52,29.97 19.3,27.76 15.3,27.76 15.05,27.51 15,27.51
  BOTTOM w0.191: J1.C4 14.23,26.49 14.01,26.71 14.01,27.13 14.38,27.51 15,27.51 ; 22.09,34.11 C5.1
OB2N: length 9.9
  BOTTOM w0.127: 19.12,29.83 19.32,30.02 19.57,30.02 20.04,30.49 20.04,35.67 20.5,36.12 20.63,36.12
  BOTTOM w0.191: C4.1 20.63,36.12 ; J1.D8 17.56,28.82 18.52,28.82 19.01,29.31 19.01,29.72 19.12,29.83
OB2P: length 9.8
  BOTTOM w0.127: 18.86,30.32 19.45,30.32 19.75,30.61 19.75,35.79 20.32,36.36 20.32,36.51
  BOTTOM w0.191: 18.86,30.32 17.83,30.32 17.58,30.07 16.96,30.07 J1.D7 ; C3.1 20.32,36.51
OB3N: length 10.8
  BOTTOM w0.127: 25.18,30.85 25.05,30.85 20.42,26.22 19.32,26.22 19.12,26.03
  BOTTOM w0.191: 19.12,26.03 19.01,25.92 19.01,25.48 18.59,25.05 17.53,25.05 J1.C8 ; C8.1 25.18,30.85
OB3P: length 10.7
  BOTTOM w0.127: 18.86,26.52 20.3,26.52 24.87,31.09 24.87,31.24
  BOTTOM w0.191: J1.C7 16.97,26.26 17.6,26.26 17.85,26.52 18.86,26.52 ; C7.1 24.87,31.24
OB_0N: length 27.2
  TOP w0.127: 32.83,45.08 32.97,45.08 37.36,40.68 37.72,40.68 37.82,40.58 U1.2
  TOP w0.191: v2(32.47,45.08) 32.83,45.08
  BOTTOM w0.127: 26.05,45.39 25.76,45.39 18.21,37.83 18.21,37.73
  BOTTOM w0.191: 26.11,45.46 26.64,45.97 26.72,46.05 27.07,46.05 27.53,45.6 27.94,45.6 28.41,46.07 28.76,46.07 29.2,45.62 29.52,45.62 29.97,46.07 30.25,46.07 30.69,45.63 31.06,45.63 31.5,46.07 31.78,46.07 32.47,45.38 v2(32.47,45.08) ; C2.2 18.21,37.73
OB_0P: length 26.9
  TOP w0.127: U1.1 37.8,41.08 37.69,40.98 37.48,40.98 33.17,45.29 33.17,45.42
  TOP w0.191: v2(33.17,45.79) 33.17,45.42
  BOTTOM w0.127: 17.87,38.04 18,38.04 25.5,45.54 25.5,45.78 25.54,45.88
  BOTTOM w0.191: 25.54,45.88 25.81,46.15 25.97,46.31 26.29,46.64 26.61,46.64 26.61,46.64 32.02,46.64 32.87,45.79 v2(33.17,45.79) ; C1.2 17.87,38.04
OB_1N: length 19.6
  TOP w0.127: 28.24,39.02 28.38,39.02 28.72,38.68 37.69,38.68 37.8,38.58 U1.6
  TOP w0.191: v2(27.89,39.02) 28.24,39.02
  BOTTOM w0.191: v2(27.89,39.02) 27.89,39.33 27.54,39.67 26.87,39.67 26.57,39.37 26.57,38.97 26.3,38.69 25.89,38.69 25.67,38.47 25.67,37.84 25.52,37.68 24.88,37.68 24.75,37.55 24.75,36.95 24.58,36.78 23.98,36.78 23.78,36.58 23.78,35.01 23.31,34.54 C6.2
OB_1P: length 19.4
  TOP w0.127: U1.5 37.81,39.08 37.71,38.98 28.84,38.98 28.59,39.22 28.59,39.37
  TOP w0.191: v2(28.59,39.73) 28.59,39.37
  BOTTOM w0.191: C5.2 22.91,34.94 23.21,35.25 23.21,36.82 26.64,40.24 27.78,40.24 28.29,39.73 v2(28.59,39.73)
OB_2N: length 21.6
  TOP w0.127: U1.4 37.8,39.58 37.69,39.69 34.1,39.69 32.2,41.58 32.08,41.58
  TOP w0.191: v2(31.7,41.58) 32.08,41.58
  BOTTOM w0.127: 21.54,36.97 21.54,37.13 25.64,41.23 25.83,41.23 25.88,41.28
  BOTTOM w0.191: v2(31.7,41.58) 31.7,41.89 31.01,42.58 30.5,42.58 30.08,42.16 29.7,42.16 29.29,42.58 28.88,42.58 28.46,42.16 28.1,42.16 27.68,42.58 27.18,42.58 26.96,42.36 26.96,41.92 26.7,41.65 26.26,41.65 25.88,41.28 ; C4.2 21.54,36.97
OB_2P: length 21.3
  TOP w0.127: U1.3 37.79,40.08 37.69,39.98 34.22,39.98 32.41,41.79 32.41,41.94
  TOP w0.191: v2(32.41,42.29) 32.41,41.94
  BOTTOM w0.127: 25.47,41.68 25.43,41.63 25.43,41.44 21.33,37.34 21.16,37.34
  BOTTOM w0.191: v2(32.41,42.29) 32.1,42.29 31.25,43.15 26.95,43.15 25.47,41.68 ; C3.2 21.16,37.34
OB_3N: length 18.3
  TOP w0.127: U1.8 37.81,37.58 37.69,37.69 35.44,37.69 33.54,35.8 31.52,35.8 31.15,36.18 31.01,36.18
  TOP w0.191: v2(30.63,36.18) 31.01,36.18
  BOTTOM w0.191: v2(30.63,36.18) 30.63,36.48 29.95,37.16 29.04,37.16 28.78,36.9 28.78,36.49 28.5,36.22 28.1,36.22 27.88,36 27.88,35.47 27.63,35.22 27.1,35.22 26.7,34.82 26.7,34.17 26.94,33.93 26.94,33.04 26.7,32.81 26.7,32.28 26.09,31.66 C8.2
OB_3P: length 18.2
  TOP w0.127: U1.7 37.84,38.08 37.74,37.99 35.32,37.99 33.42,36.09 31.65,36.09 31.34,36.4 31.34,36.53
  TOP w0.191: v2(31.34,36.88) 31.34,36.53
  BOTTOM w0.191: C7.2 25.68,32.07 26.13,32.51 26.13,35.06 28.8,37.73 30.19,37.73 31.03,36.88 v2(31.34,36.88)
PWDN: length 24.6
  TOP w0.191: J18.2 21.97,51.03 22.53,51.59 26.77,51.59 30.33,48.03 35.25,48.03 39.64,43.65 U1.52
RES1: length 94.5
  SIGNAL w0.178: J2.A1 69.29,55.02 52.47,55.02 49.65,52.2 24.26,52.2 23.35,53.1 19.15,53.1 7.05,41.01 7.05,24.08 J1.A1
RXDET: length 19.6
  TOP w0.191: U1.22 40.14,22.22 42.29,20.07 J21.2 J25.1
SCL: length 48
  TOP w0.191: J14.1 J8.2 28.55,58.32 31.34,58.32 U2.6 ; U1.50 40.64,43.92 36.13,48.43 31.91,48.43 30.58,49.75 30.58,51.05 31.47,51.94 33.86,51.94 34.67,51.13 J38.3
  BOTTOM w0.191: J38.3 U2.6
SCLC: length 85.9
  SIGNAL w0.178: J1.C1 10.42,26.49 8.46,28.44 8.46,40.62 18.92,51.08 50.61,51.08 51.43,51.9 61.34,51.9 62.07,51.17 69.64,51.17 70.31,50.5 J2.C1
SDA: length 34.7
  TOP w0.191: J38.4 33.33,48.84 37.12,48.84 41.14,44.81 U1.49 ; U2.5 31.09,56.03 22.63,56.03 J15.1 J9.2
  BOTTOM w0.191: J38.4 U2.5
SDAC: length 82.3
  SIGNAL w0.178: J2.C2 68.57,50.83 60.18,50.83 59.56,51.45 51.93,51.45 51.14,50.66 44.13,50.66 42.45,48.98 26.58,48.98 25.96,48.36 18.46,48.36 9.31,39.21 9.31,29.47 11.2,27.58 12.32,27.58 12.99,26.91 12.99,25.09 J1.C2
SDTH: length 20.9
  TOP w0.191: J27.1 J24.2 52.05,25.67 44.95,25.67 43.23,27.39 43.23,30.45 42.14,31.54 U1.26
VACT: length 99.7
  SIGNAL w0.762: 20.32,31.83 23.69,31.83 37.61,45.75 53.67,45.75 60.88,38.54 67.51,38.54 70.38,41.41 70.38,44.57 J2.D1 72.43,46.76 72.43,50.12 J2.B1 ; 20.32,31.83 18.55,33.61 13.48,33.61 12.24,32.36 J1.D1 ; 20.32,31.83 20.35,31.81 20.35,25.33 19.04,24.02 13.57,24.02 J1.B1
VIH: length 16.1
  TOP w0.635: R37.2 v1(35.57,64.42) ; R35.2 v1(38.88,64.42)
  TOP w0.762: D1.1 v1(71.08,3.35)
  BOTTOM w0.508: R3.2 v1(22.72,67.67) ; v1(35.28,72.14) 35.28,72.9 R23.1 ; R39.2 v1(40.13,56.9) ; R2.2 v1(7.25,60.22) ; R4.2 v1(20.59,56.53) ; R1.2 v1(7.25,50.44) ; R42.2 v1(50.66,70.09) ; R5.2 v1(50.91,61.58) ; R22.2 v1(20.72,46.88)
  BOTTOM w0.635: R45.2 v1(29.61,4.59) ; R30.2 v1(53.86,6.11) ; R6.2 v1(29.35,13.1) ; R26.2 v1(41.29,14.75) ; R48.2 v1(41.54,6.11) ; R32.2 v1(52.72,21.48)
  vias: v1(1.27,52.07) v1(1.27,50.8) v1(1.27,49.53) v1(1.27,48.26) v1(2.54,52.07) v1(2.54,50.8) v1(2.54,49.53) v1(2.54,48.26) v1(3.81,52.07) v1(3.81,50.8) v1(3.81,49.53) v1(3.81,48.26) v1(5.08,49.53) v1(5.08,48.26) v1(6.35,49.53) v1(24.13,12.7) v1(24.13,11.43) v1(24.13,10.16) v1(24.13,8.89) v1(24.13,7.62) v1(25.4,12.7) v1(25.4,11.43) v1(25.4,10.16) v1(25.4,8.89) v1(25.4,7.62) v1(26.67,12.7) v1(26.67,11.43) v1(26.67,10.16) v1(26.67,8.89) v1(26.67,7.62)
VMAN: length 74.2
  SIGNAL w0.762: J1.D2 12.9,28.8 11.65,28.8 10.61,29.84 10.61,36.27 19.73,45.4 24.12,45.39 27.96,47.96 53.86,47.96 54.56,48.66 58.85,48.66 60.09,47.42 68.18,47.42 J2.D2
WP: length 4
  BOTTOM w0.191: R40.2 R39.1 37.96,55.74 37.21,54.99
N469503: length 1.7
  BOTTOM w0.191: R7.2 10.81,52.94 J6.3
N469537: length 1.9
  TOP w0.381: D1.2 66.08,3.35 R19.2
N469595: length 1.8
  BOTTOM w0.191: J6.1 5.95,52.72 R1.1
N469811: length 1.7
  BOTTOM w0.191: R8.2 10.81,62.72 J7.3
N469819: length 1.7
  BOTTOM w0.191: R9.2 19.16,65.17 J8.3
N469827: length 1.7
  BOTTOM w0.191: J9.3 24.14,59.04 R10.2
N469835: length 1.7
  BOTTOM w0.191: J10.3 47.36,59.07 R11.2
N469843: length 1.7
  BOTTOM w0.191: J11.3 32.91,15.61 R12.2
N469847: length 1.8
  BOTTOM w0.191: J10.1 52.21,59.29 R5.1
N469855: length 1.8
  BOTTOM w0.191: R6.1 28.05,15.38 J11.1
N469867: length 1.8
  BOTTOM w0.191: R4.1 19.29,58.82 J9.1
N469875: length 1.8
  BOTTOM w0.191: R3.1 24.02,65.39 J8.1
N469883: length 1.8
  BOTTOM w0.191: J7.1 5.95,62.5 R2.1
N469925: length 1.8
  BOTTOM w0.191: R14.2 10.56,58.43 J13.2
N469953: length 1.8
  BOTTOM w0.191: R13.2 10.56,48.66 J12.2
N469977: length 1.8
  BOTTOM w0.191: R15.2 19.42,69.45 19.18,69.22
N470001: length 1.8
  BOTTOM w0.191: R16.2 23.89,54.75 J15.2
N470025: length 2.3
  BOTTOM w0.191: J16.2 49.01,64.76 R17.2
N470049: length 1.8
  BOTTOM w0.191: J17.2 32.65,11.32 R18.2
N470163: length 3.6
  TOP w0.381: J30.1 64.77,3.36 R19.1
N470231: length 1.8
  BOTTOM w0.191: R22.1 19.42,49.52 J18.1
N470235: length 1.7
  BOTTOM w0.191: 24.51,49.53 24.53,49.52 R21.1
N470313: length 1.8
  BOTTOM w0.191: J19.1 34.02,71.13 R23.2
N470329: length 1.8
  BOTTOM w0.191: R24.2 39.13,71.13 J19.3
N470353: length 1.7
  BOTTOM w0.191: J21.3 44.85,17.26 R25.2
N470405: length 1.8
  BOTTOM w0.191: J21.1 39.99,17.03 R26.1
N470413: length 1.8
  BOTTOM w0.191: J25.2 44.59,12.97 R27.2
N470453: length 2
  BOTTOM w0.191: R28.2 52.94,12.94 J22.2
N470501: length 1.7
  BOTTOM w0.191: R29.2 57.42,8.62 J23.3
N470525: length 1.8
  BOTTOM w0.191: R30.1 52.56,8.4 J23.1
N470567: length 1.7
  BOTTOM w0.191: R31.2 56.28,23.99 J24.3
N470597: length 1.8
  BOTTOM w0.191: R32.1 51.42,23.76 J24.1
N470693: length 1.8
  BOTTOM w0.191: J27.2 56.02,19.7 R34.2
N470705: length 1.8
  BOTTOM w0.191: R33.2 57.16,4.46 J26.2
N472799: length 1.7
  BOTTOM w0.191: R41.2 47.1,67.58 J28.3
N472807: length 1.8
  BOTTOM w0.191: J28.1 51.96,67.8 R42.1
N472815: length 1.8
  BOTTOM w0.191: R43.2 47.36,71.87 J29.2
N477528: length 1.7
  BOTTOM w0.191: R44.2 33.16,7.1 J31.3
N477536: length 1.8
  BOTTOM w0.191: J31.1 28.31,6.87 R45.1
N477544: length 1.8
  BOTTOM w0.191: R46.2 32.91,2.81 J32.2
N478062: length 1.7
  BOTTOM w0.191: R47.2 45.1,8.62 J33.3
N478086: length 1.8
  BOTTOM w0.191: R48.1 40.24,8.4 J33.1
N478094: length 1.8
  BOTTOM w0.191: J34.2 44.85,4.33 R49.2

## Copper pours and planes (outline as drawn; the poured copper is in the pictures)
GND on TOP: 69.59,26.95 69.59,20.98 70.92,19.65 80.89,19.65 81.27,20.03 81.27,26.06 80.39,26.95
GND on BOTTOM: 42.92,34.19 42.92,40.73 42.33,41.32 39,41.32 38.38,40.7 38.38,34.12 39.1,33.4 42.12,33.4
GND on GND1, GND2: 10.16,0.64 10.16,11.43 0.64,11.43 0.64,64.77 10.16,64.77 10.16,74.29 73.66,74.29 73.66,64.77 83.18,64.77 83.18,10.16 73.66,10.16 73.66,0.64
VDD on TOP: 64.26,19.71 64.26,14.06 65.97,12.34 81.02,12.34 81.4,12.72 81.4,17.8 81.02,18.19 70.73,18.19 68.83,20.09 64.64,20.09
VDD on BOTTOM: 64.26,19.71 64.26,14.07 65.99,12.34 81.02,12.34 81.4,12.72 81.4,17.8 81.02,18.19 70.73,18.19 68.83,20.09 64.64,20.09
VDD on BOTTOM: 38.01,41.11 38.66,41.76 40.93,41.76 41.13,41.95 41.13,43.49 40.76,43.87 37.1,43.87 36.01,42.77 36.01,36.89 36.03,36.91 36.03,32.3 36.83,31.5 43.56,31.5 44.3,32.24 44.3,39.35 44.19,39.46 43.4,39.46 43.3,39.35 43.3,33.52 42.55,32.77 38.61,32.77 38.01,33.36
VDD on PWR: 33.1,0.64 33.1,24.92 22.05,24.92 22.05,53.53 0.64,53.53 0.64,64.77 10.16,64.77 10.16,74.29 73.66,74.29 73.66,64.77 83.18,64.77 83.18,10.16 73.66,10.16 73.66,0.64
VIN on TOP: 69.41,31.87 81.12,31.87 81.12,31.84 81.41,31.54 81.41,28.29 81.13,28.01 68.75,28.01 67.69,26.96 67.69,23.78 66.89,22.97 62.97,22.97 62.13,23.8 62.13,28.51 65.51,31.88 69.4,31.88
VIN on BOTTOM: 64.02,22.7 81.17,22.7 82.99,24.52 82.99,28.92 80.86,31.05 64.03,31.05 62.56,29.58 62.56,24.16
VIN on SIGNAL: 40.53,23.24 80.65,23.24 81.79,24.38 81.79,31.85 78.61,35.03 59.29,35.03 55.08,39.24 42.16,39.24 38.73,35.81 38.73,25.03
VIH on PWR: 10.16,0.64 10.16,11.43 0.64,11.43 0.64,53.02 21.54,53.02 21.54,24.41 32.59,24.41 32.59,0.64
VIH on SIGNAL: 40.99,22.61 71.63,22.61 73.03,21.21 73.03,1.78 71.88,0.64 22.54,0.64 21.4,1.78 21.4,19.37 24.26,22.22
VIH on SIGNAL: 0.64,45.34 0.64,64.77 0.76,64.77 0.72,64.73 10.23,64.73 10.23,73.79 50.16,73.79 53.34,70.61 53.34,58.55 48.13,53.34 26.29,53.34 25.53,54.1 18.03,54.1 9.27,45.34

Small or netless copper shapes (teardrops, artwork), in the pictures only: 37 on TOP, 108 on BOTTOM

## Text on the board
BOTTOM: BOTTOM
Ref Des/Silkscreen Bottom: MAY-2014 | PD-14-0265
TOP: TOP
Ref Des/Silkscreen Top: DEMB1/ | DEMB0/ | AD1 | AD0 | DEMA0/SDA | PWDN | EQA1 | EQA0 | DEMA1/ | SCL | ENSMB | MODE_B | RXDET | PIN | 1 | SD_TH | RES | AD2/ | AD3/ | 0 | EQB1 | EQB0 | R | VDDSEL | VIN | VIH | VDD | DONE | SDA | GND | FLOAT = NO SHUNT | LOCATION | PIN CONTROL SHUNT | DS125BR401A SAS3 BRD | SV601073 | REV.1
GND1: GND-1
PWR: PWR
SIGNAL: SIGNAL
GND2: GND-2
PAGE_OUTLINE: TAHOE
User.5: DS125BR401A SAS3 EVAL BOARD
User.12: 305-PD-14-0265
User.13: 1 | 7 MIL SINGLE-ENDED TRACES REQUIRE 50 OHM +/-10% IMPEDANCE ON INNER LAYER. | 5 MIL TRACEWIDTH AND 6.5MIL AIRGAP TRACES REQUIRE 100 OHM +/-5% | 7.5 MIL SINGLE-ENDED TRACES REQUIRE 50 OHM +/-10% IMPEDANCE ON TOP AND BOTTOM LAYER. | 4. FINISH: SOFT IMMERSION GOLD. | 12. ANY CHANGES MADE BY THE PCB FABRICATOR TO THE FILM OR THE GERBR FILES MUST BE | DIFFERENTIAL IMPEDANCE ON BOTH TOP AND BOTTOM LAYERS. | 10. BOARD DIMENSIONS ARE IN INCHES[MM]. | 11. NO VENDOR LOGO OR NAME ON THE BOARD. | 13. REMOVE THE NON-FUNCTIONAL PADS IN ALL INNER LAYERS. | 14. THIS BOARD MUST BE ROHS COMPLAINT. | 6. SILK SCREENS BOTH SIDES SHALL BE WHITE. | 5. SOLDER MASK BOTH SIDES SHALL BE VENDOR'S STANDARD. | 3. LAYER STACK-UP AS SHOWN. | 9. BOARD THICKNESS : 62 MILS +/- 10%.. | 8. EACH ASSEMBLED BOARD MUST BE PACKAGED IN A ESD BAG AND SEALED WITH AN ESD LABEL. | 7. BOARD TWIST AND WARP SHALL NOT EXCEED 4MILS/LINEAR INCH. | 1. ALL LAYERS TO BE FR408 (Er =3.8) MATERIAL,ROHS COMPLAINT. | 2. ALL COPPER LAYERS SHALL BE 1 OUNCE (1.4 MIL) FINISHED THICKNESS. | (THE BOARD THICKNESS TO BE AS CLOSE AS POSSIBLE TO 62 MIL) | APPROVED BY PACTRON. | IMPEDANCE DETAILS: | NOTES:
User.39: SILKSCREEN TOP
User.40: SILKSCREEN BOTTOM
User.41: SOLDERMASK TOP
User.42: SOLDERMASK BOTTOM
User.43: SOLDERPASTE TOP
User.44: SOLDERPASTE BOTTOM
User.45: 408 747 1239 (fax) | 1149 Tasman Drive, | Sunnyvale Ca 94089 | 408 747 1237 (phone) | ASSEMBLYTOP | ASSEMBLY BOTTOM | NAME : DS125BR401A SAS3 EVAL BOARD | LAYER  : | DATE : MAR 2014 | TEXAS AND INSTRUMENTS | JOB : 305-PD-14-0265 | SHEET | REV.1 | FAB | FIGURE | SIZE | 10.0 | 14.57 | 22.44 | 40.0 | 55.0 | 86.61 | 166.0 | DRILL CHART: TOP to BOTTOM | ALL UNITS ARE IN MILS | TOLERANCE | +3.0/-10.0 | +2.0/-2.0 | +3.0/-3.0 | +4.0/-4.0 | PLATED | QTY | 170 | 72 | 12 | 85 | 6 | 2 | 4 | (X-SECTION VIEW / 6 LAYER BOARD) | LAYER STACK-UP | LAYER 3 PWR | LAYER 4 SIGNAL | LAYER 1 TOP | LAYER 2 GND-1 | LAYER 6 BOTTOM | LAYER 5 GND-2 | PRIMARY SIDE | SECONDARY SIDE | 1.30 MILS | 1.58 MILS | 5.00 MILS PREPEG | 4.50 MILS PREPEG | 30.00 MILS PREPEG
